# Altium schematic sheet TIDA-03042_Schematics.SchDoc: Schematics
size 431 x 279 mm; Date: Not shown in title block; ApprovedBy: Not shown in title block; CheckedBy: Not shown in title block; Author: Not shown in title block; CompanyName: Not shown in title block; Engineer: NING TANG; Organization: Not shown in title block; Address1: Not shown in title block; Address2: Not shown in title block; Address3: Not shown in title block; Address4: Not shown in title block; DocumentNumber: 1; Revision: Use project parameter SCH_Rev; SheetNumber: 1; SheetTotal: 2; PageSetup: Record=PageOptions¦CenterHorizontal=True¦CenterVertical=True¦PrintScale=1.00¦XCorrection=1.00¦YCorrection=1.00¦PrintKind=0¦BorderSize=5000000¦LeftOffset=0¦BottomOffset=0¦Orientation=2¦PaperLength=1000¦PaperWidth=1000¦Scale=100¦PaperSource=15¦PrintQuality=600¦MediaType=1¦DitherType=10¦PaperKind=Letter¦PrintScaleMode=1
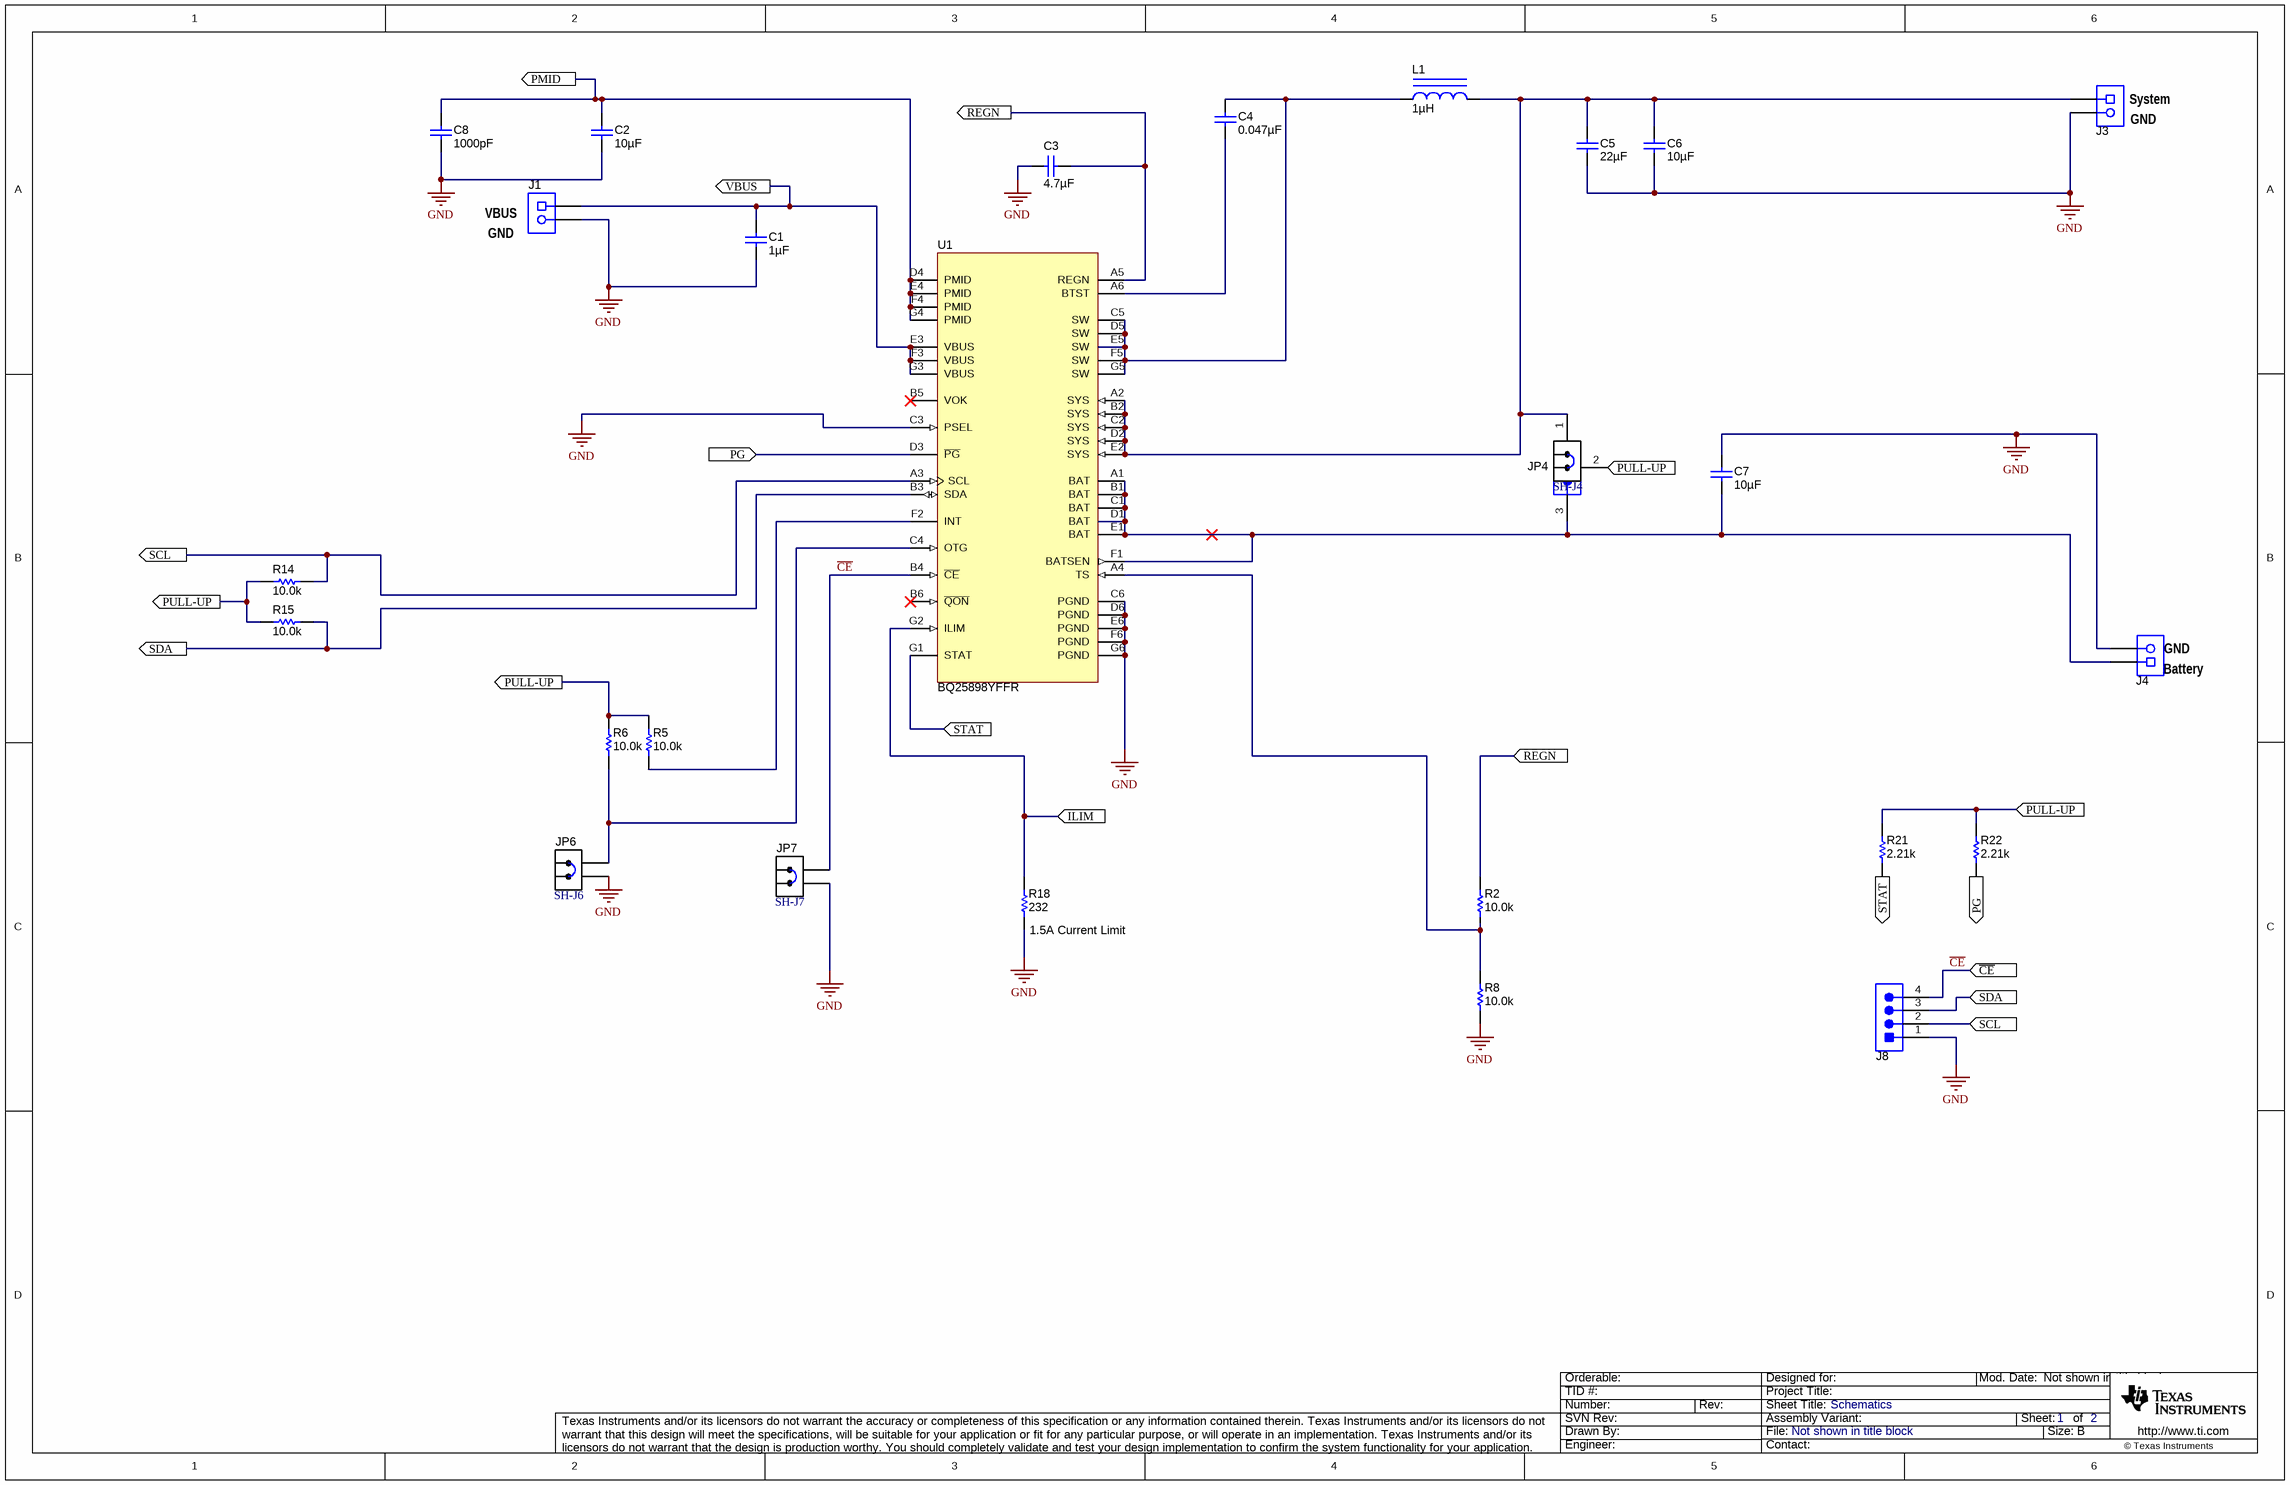
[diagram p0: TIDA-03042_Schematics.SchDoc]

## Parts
C1  ValueDisplayed: 1µF  [0805L]  (hidden comment: GRM219R71E105KA88D)
C2  ValueDisplayed: 10µF  [0805L]  (hidden comment: C2012X5R1E106K125AB)
C3  ValueDisplayed: 4.7µF  [0603_HV]  (hidden comment: GRM188R61C475KAAJ)
C4  ValueDisplayed: 0.047µF  [0402L]  (hidden comment: GRM155R71E473KA88D)
C5  ValueDisplayed: 22µF  [0805L]  (hidden comment: C2012X5R1C226M125AC)
C6  ValueDisplayed: 10µF  [0805L]  (hidden comment: GRM21BR71A106KE51L)
C7  ValueDisplayed: 10µF  [0805L]  (hidden comment: GRM21BR71A106KE51L)
C8  ValueDisplayed: 1000pF  [0603]  (hidden comment: GRM188R71E102KA01D)
J1  1727010  [PhoenixConact_1727010]  (value not drawn)
J3  1727010  [PhoenixConact_1727010]  (value not drawn)
J4  1727010  [PhoenixConact_1727010]  (value not drawn)
J8  22-05-3041  [CONN_22-05-3041]  (value not drawn)
JP4  PEC03SAAN  [CONN_PEC03SAAN]  (value not drawn)
JP6  PEC02SAAN  [CONN_PEC02SAAN]  (value not drawn)
JP7  PEC02SAAN  [CONN_PEC02SAAN]  (value not drawn)
L1  ValueDisplayed: 1µH  [WE-PMCI_0805]  (hidden comment: 74479275210)
R2  value 10.0k  [0402]  (hidden comment: CRCW040210K0FKED)
R5  value 10.0k  [0402]  (hidden comment: CRCW040210K0FKED)
R6  value 10.0k  [0402]  (hidden comment: CRCW040210K0FKED)
R8  value 10.0k  [0402]  (hidden comment: CRCW040210K0FKED)
R14  value 10.0k  [0402]  (hidden comment: CRCW040210K0FKED)
R15  value 10.0k  [0402]  (hidden comment: CRCW040210K0FKED)
R18  ValueDisplayed: 232  [0402]  (hidden comment: CRCW0402232RFKED)
R21  value 2.21k  [0402]  (hidden comment: CRCW04022K21FKED)
R22  value 2.21k  [0402]  (hidden comment: CRCW04022K21FKED)
SH-J4  SNT-100-BK-G  [SNT-100-BK-G]  (value not drawn)
SH-J6  SNT-100-BK-G  [SNT-100-BK-G]  (value not drawn)
SH-J7  SNT-100-BK-G  [SNT-100-BK-G]  (value not drawn)
U1  BQ25898YFFR  [YFF0042-C01]

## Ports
ILIM, PG, PMID, PULL-UP, REGN, SCL, SDA, STAT, VBUS, ~{CE}

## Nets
GND: C1.2 C2.2 C3.2 C5.2 C6.2 C7.1 C8.1 J1.2 J3.2 J4.2 J8.1 JP6.1 JP7.1 R8.1 R18.1 U1.C3(PSEL) U1.C6(PGND) U1.D6(PGND) U1.E6(PGND) U1.F6(PGND) U1.G6(PGND)
~{CE}: J8.4 JP7.2 U1.B4(~{CE}) ; port ~{CE}
ILIM: R18.2 U1.G2(ILIM) ; port ILIM
PG: R22.1 U1.D3(~{PG}) ; port PG
PMID: C2.1 C8.2 U1.D4(PMID) U1.E4(PMID) U1.F4(PMID) U1.G4(PMID) ; port PMID
PULL-UP: JP4.2 R5.2 R6.2 R14.1 R15.1 R21.2 R22.2 ; port PULL-UP
REGN: C3.1 R2.2 U1.A5(REGN) ; port REGN
SCL: J8.2 R14.2 U1.A3(SCL) ; port SCL
SDA: J8.3 R15.2 U1.B3(SDA) ; port SDA
STAT: R21.1 U1.G1(STAT) ; port STAT
VBUS: C1.1 J1.1 U1.E3(VBUS) U1.F3(VBUS) U1.G3(VBUS) ; port VBUS
NetC4_1: C4.1 L1.1 U1.C5(SW) U1.D5(SW) U1.E5(SW) U1.F5(SW) U1.G5(SW)
NetC4_2: C4.2 U1.A6(BTST)
NetC5_1: C5.1 C6.1 J3.1 JP4.1 L1.2 U1.A2(SYS) U1.B2(SYS) U1.C2(SYS) U1.D2(SYS) U1.E2(SYS)
NetC7_2: C7.2 J4.1 JP4.3 U1.A1(BAT) U1.B1(BAT) U1.C1(BAT) U1.D1(BAT) U1.E1(BAT) U1.F1(BATSEN)
NetJP6_2: JP6.2 R6.1 U1.C4(OTG)
NetR2_1: R2.1 R8.2 U1.A4(TS)
NetR5_1: R5.1 U1.F2(INT)

Not connected (* = marked no-connect by the designer): U1 B5(VOK)* B6(~{QON})*

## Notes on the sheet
- (near J3) System
- (near J3) GND
- (near J1) VBUS
- (near J1) GND
- (near J4) GND
- (near J4) Battery
- (near R18) 1.5A Current Limit

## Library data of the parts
C1 = GRM219R71E105KA88D: CAP, CERM, 1 µF, 25 V, +/- 10%, X7R, 0805; Manufacturer: MuRata; Polarized: N; CompType: Capacitor; Value: 1uF; U/M: EA; Cap_F: 0.000001; Tolerance_%: 10; Value1: Unknown; VDC_V: 25; Value2: 25V; TaMin_C: -55; TaMax_C: 125; Cap_Case: 0805
C2 = C2012X5R1E106K125AB: CAP, CERM, 10uF, 25V, +/-10%, X5R, 0805; Manufacturer: TDK; Polarized: N; CompType: Capacitor; U/M: EA; Cap_F: 0.00001; Tolerance_%: 10; Value1: Unknown; VDC_V: 25; TaMin_C: -55; TaMax_C: 85; Cap_Case: 0805
C3 = GRM188R61C475KAAJ: CAP, CERM, 4.7uF, 16V, +/-10%, X5R, 0603; Manufacturer: MuRata; Polarized: N; CompType: Capacitor; U/M: EA; Cap_F: 0.0000047; Tolerance_%: 10; Value1: Unknown; VDC_V: 16; TaMin_C: -55; TaMax_C: 85; Cap_Case: 0603
C4 = GRM155R71E473KA88D: CAP, CERM, 0.047uF, 25V, +/-10%, X7R, 0402; Manufacturer: MuRata; Polarized: N; CompType: Capacitor; U/M: EA; Cap_F: 0.000000047; Tolerance_%: 10; Value1: Unknown; VDC_V: 25; TaMin_C: -55; TaMax_C: 125; Cap_Case: 0402
C5 = C2012X5R1C226M125AC: CAP, CERM, 22 µF, 16 V, +/- 20%, X5R, 0805; Manufacturer: TDK; Polarized: N; CompType: Capacitor; Value: 22uF; U/M: EA; Cap_F: 0.000022; Tolerance_%: 20; Value1: Unknown; VDC_V: 16; Value2: 16V; TaMin_C: -55; TaMax_C: 85; Cap_Case: 0805; SizeArea_mm2: 2.5; SizeAreaWB_mm2: 6.75; SizeX_mm: 2; SizeY_mm: 1.25; SizeZ_mm: 1.45; AEC Category: Q200
C6 C7 = GRM21BR71A106KE51L: CAP, CERM, 10 µF, 10 V, +/- 10%, X7R, 0805; Manufacturer: MuRata; Polarized: N; CompType: Capacitor; Value: 10uF; U/M: EA; Cap_F: 0.00001; Tolerance_%: 10; ESR_ohm: 0.003; Value1: 0.003 ohm; Value2: 10V; TaMin_C: -55; TaMax_C: 125; Cap_Case: 0805
C8 = GRM188R71E102KA01D: CAP, CERM, 1000 pF, 25 V, +/- 10%, X7R, 0603; Manufacturer: MuRata; Polarized: N; CompType: Capacitor; Value: 1000pF; U/M: EA; Cap_F: 0.000000001; Tolerance_%: 10; Value1: Unknown; VDC_V: 25; Value2: 25V; TaMin_C: -55; TaMax_C: 125; SizeArea_mm2: 1.28; SizeAreaWB_mm2: 4.68; SizeX_mm: 1.6; SizeY_mm: 0.8; SizeZ_mm: 1; AEC Category: Q200
J1 J3 J4 = 1727010: Conn Term Block, 2POS, 3.81mm, TH; Manufacturer: Phoenix Contact; SymbolCreator: a0412235; Value: 2x1; CompType: Terminal Block; U/M: EA
J8 = 22-05-3041: Header, 100mil, 4x1, R/A, TH; Manufacturer: Molex; SymbolCreator: a0412235; U/M: EA
JP4 = PEC03SAAN: Header, 100mil, 3x1, Tin plated, TH; Manufacturer: Sullins Connector Solutions; SymbolCreator: a0799628; U/M: EA
JP6 JP7 = PEC02SAAN: Header, 100mil, 2x1, Tin plated, TH; Manufacturer: Sullins Connector Solutions; SymbolCreator: a0412235; U/M: EA
L1 = 74479275210: Inductor, Shielded, 1 µH, 1.8 A, 0.078 ohm, SMD; Manufacturer: Wurth Elektronik; Value: 1uH; Ind_H: 1.0E-6; Imax_A: 1.8; Irms: 1.8A @ 40C rise; Isat: 2.1A @ 30% inductance drop; DCR_ohm: 0.078; Value2: 1.8A; AEC Category: Q200; AEC Qualified: N; SizeAreaWB_mm2: 6.75; SizeArea_mm2: 2.5; SizeX_mm: 2; SizeY_mm: 1.25; SizeZ_mm: 1
R2 R5 R6 R8 R14 R15 = CRCW040210K0FKED: RES, 10.0k ohm, 1%, 0.063W, 0402; Manufacturer: Vishay-Dale; CompType: Resistor; Res_ohm: 10000; Value_Code: 10k0; Tolerance_%: 1; Power_W: 0.063; VDC_V: 50; TempCo: 100 ppm/C; EIA_Code: E96; U/M: EA
R18 = CRCW0402232RFKED: RES, 232, 1%, 0.063 W, 0402; Manufacturer: Vishay-Dale; CompType: Resistor; Value: 232; Value_Code: 232R; Tolerance_%: 1; Power_W: 0.063; Value2: 0.063W; VDC_V: 50; TempCo: 100 ppm/C; EIA_Code: E96; U/M: EA; SizeArea_mm2: 0.5; SizeZ_mm: 0.6; AEC Category: Q200
R21 R22 = CRCW04022K21FKED: RES, 2.21k ohm, 1%, 0.063W, 0402; Manufacturer: Vishay-Dale; CompType: Resistor; Res_ohm: 2210; Value_Code: 2k21; Tolerance_%: 1; Power_W: 0.063; VDC_V: 50; TempCo: 100 ppm/C; EIA_Code: E96; U/M: EA
SH-J4 SH-J6 SH-J7 = SNT-100-BK-G: Shunt, 100mil, Gold plated, Black; Manufacturer: Samtec; Alternate Manufacturer: 3M; Alternate PartNumber: 969102-0000-DA; Value: 1x2; Note: You can "mate" this to a header by matching the designator.  i.e. use SH-J3 for header J3
U1 = BQ25898YFFR: I2C Controlled 4A Single Cell NVDC Power Path Management with MaxChargeTM High Voltage Adapter Support, YFF0042-C01; Alternate PartNumber: BQ25898YFFT; Manufacturer: Texas Instruments; SymbolCreator: Altium; CompType: IC; U/M: EA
